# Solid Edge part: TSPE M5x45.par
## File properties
Title: 1320201990
Subject: Vite TSPEI M5x45
Author: g_deluca
Template: RBuno.par
Last saved by: g_deluca
Revision: 17
Application: Solid Edge
Material: Classe 10.9
Tipo di contenuto documento: 0
Company: EFFEBI S.p.A.
Codice: Codice
Indice rev.: Rev.
Data rev.: Data rev.
Firma rev.: Firma rev.
Descrizione rev.: Descrizione rev.
Densità: 7860.000 kg/m^3
Precisione: 0.99
Document Number: UNI 5933
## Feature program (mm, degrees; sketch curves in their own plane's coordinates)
sketch for "unnamed RevolvedProtrusion 1" plane through (0, 0, 0) normal (0, -1, 0) x-axis (1, 0, 0)
revolve "unnamed RevolvedProtrusion 1" add finite 360 deg
sketch for "unnamed Protrusion 1" plane through (0, 0, 2.8) normal (0, 0, 1) x-axis (1, 0, 0)
  circle centre (0, 0) radius 2.5
extrude "unnamed Protrusion 1" add finite 45 along -normal
sketch for "ExtrudedCutout_1" plane through (0, 0, 2.8) normal (0, 0, 1) x-axis (1, 0, 0)
  line (-1.5, 0.866) -> (-1.5, -0.866)
  line (0, -1.7321) -> (-1.5, -0.866)
  line (0, -1.7321) -> (1.5, -0.866)
  line (1.5, 0.866) -> (1.5, -0.866)
  line (1.5, 0.866) -> (0, 1.7321)
  line (-1.5, 0.866) -> (0, 1.7321)
extrude "ExtrudedCutout_1" cut finite 3 along -normal
thread "unnamed Thread 1"
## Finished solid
Body 1: solid body, 12 faces, 22 edges, 12 vertices.
  Faces by surface: plane 9, cylinder 2, cone 1
  Edges by curve: line 18, circle 4
Bounding box of the edges (mm): 10.000 x 10.000 x 45.000, from (-5, -5, -42.2) to (5, 5, 2.8).
Cylindrical faces by radius (mm): R2.5 x1, R5 x1
Conical faces (half-angle, radius in mm at the cone's reference point): 45 deg R2.5 x1
Planar faces by outward normal: +x 1, +z 2, -x 1, -z 1, oblique 4
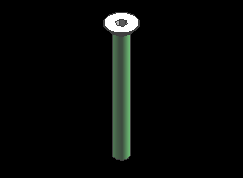
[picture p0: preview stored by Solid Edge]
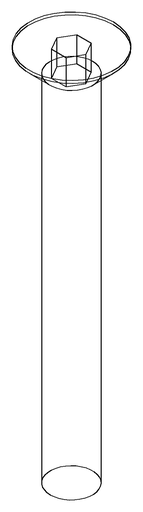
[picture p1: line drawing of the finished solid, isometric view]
